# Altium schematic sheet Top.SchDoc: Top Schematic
size A4; Date: Not used; ApprovedBy: Not used; CheckedBy: Not used; Author: Not used; CompanyName: STMicroelectronics; DrawnBy: Not used; Engineer: Not used; Organization: Not used; Address1: Not used; Address2: Not used; Address3: Not used; Address4: Not used; DocumentNumber: Not used; Revision: Not used; SheetNumber: 2; SheetTotal: 6
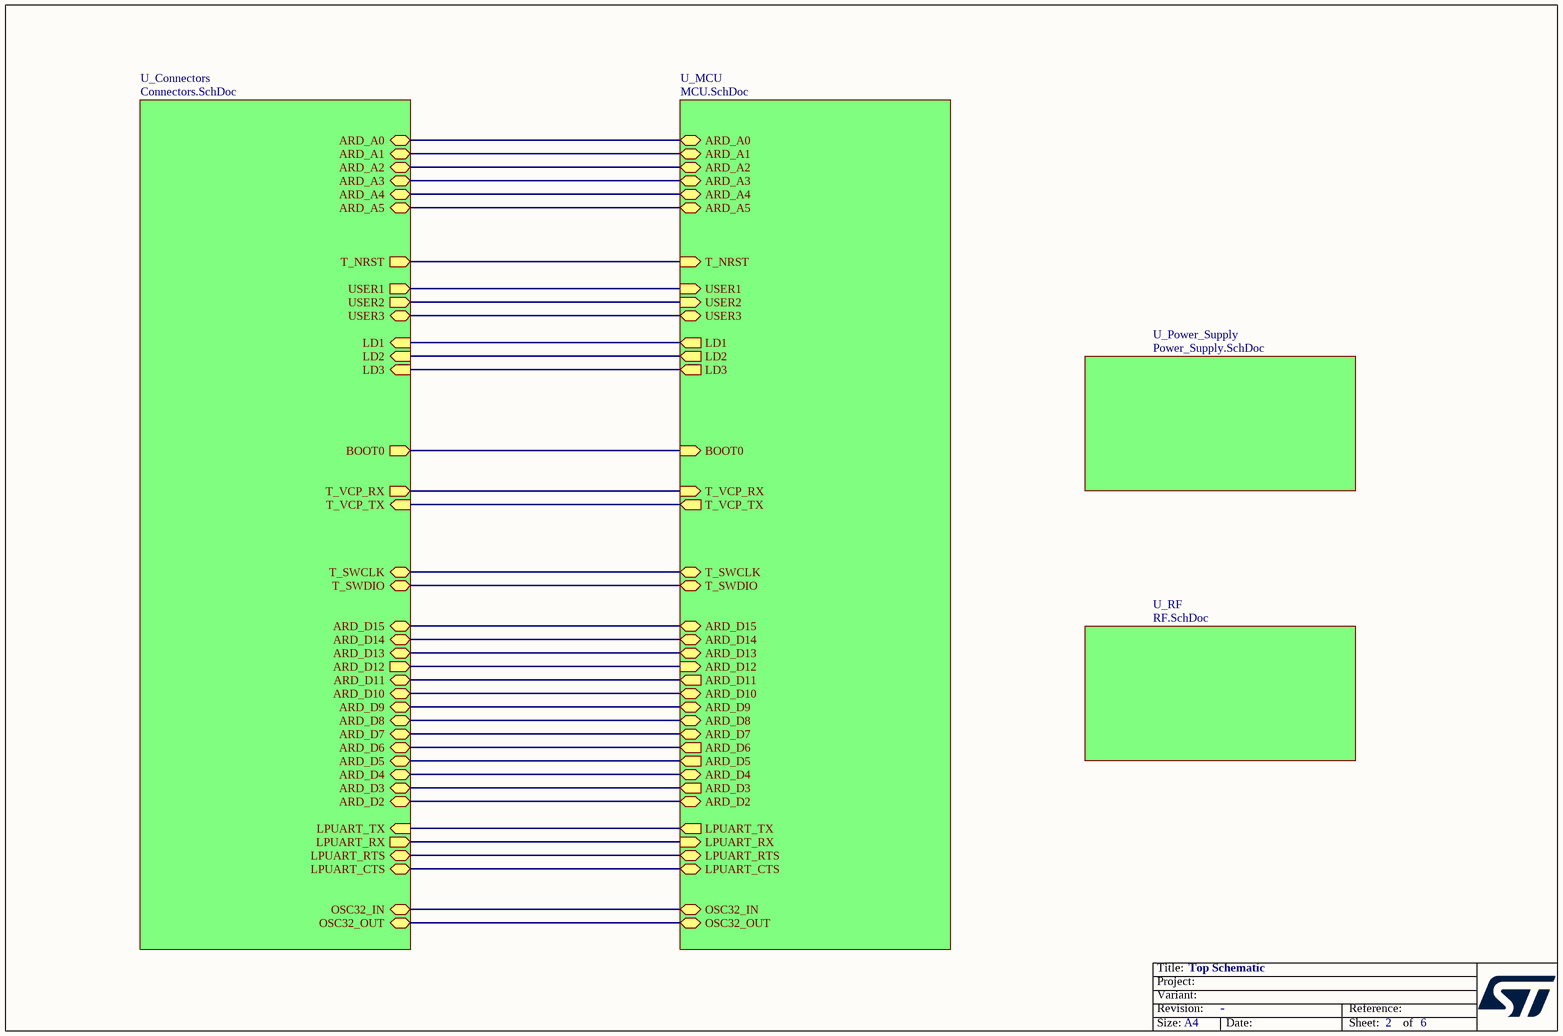
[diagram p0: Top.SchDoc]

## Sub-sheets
U_Connectors = Connectors.SchDoc: LD3 (in), LD1 (in), T_VCP_TX (in), T_SWCLK (bidir), T_SWDIO (bidir), T_VCP_RX (out), T_NRST (out), LD2 (in), OSC32_IN (bidir), OSC32_OUT (bidir), USER2 (out), USER1 (out), BOOT0 (out), ARD_D2 (bidir), USER3 (bidir), ARD_D9 (bidir), ARD_D13 (bidir), ARD_D10 (bidir), ARD_D12 (out), ARD_D14 (bidir), ARD_D15 (bidir), ARD_D11 (bidir), ARD_D8 (bidir), ARD_A1 (bidir), ARD_A0 (bidir), ARD_A2 (bidir), ARD_A3 (bidir), ARD_A4 (bidir), ARD_A5 (bidir), ARD_D7 (bidir), ARD_D6 (bidir), ARD_D3 (bidir), ARD_D4 (bidir), ARD_D5 (bidir), LPUART_TX (in), LPUART_RX (out), LPUART_RTS (bidir), LPUART_CTS (bidir)
U_MCU = MCU.SchDoc: T_NRST (in), LD2 (out), LD3 (out), LD1 (out), T_VCP_RX (in), T_SWCLK (bidir), T_SWDIO (bidir), T_VCP_TX (out), USER2 (in), USER1 (in), OSC32_OUT (bidir), OSC32_IN (bidir), BOOT0 (in), ARD_D2 (bidir), USER3 (bidir), ARD_D9 (bidir), ARD_D14 (bidir), ARD_D15 (bidir), ARD_D8 (bidir), ARD_D12 (in), ARD_D13 (bidir), ARD_A3 (bidir), ARD_A2 (bidir), ARD_A1 (bidir), ARD_A0 (bidir), ARD_A4 (bidir), ARD_A5 (bidir), ARD_D5 (out), ARD_D3 (out), ARD_D6 (out), ARD_D11 (out), ARD_D10 (bidir), ARD_D7 (bidir), ARD_D4 (bidir), LPUART_TX (out), LPUART_RX (in), LPUART_RTS (bidir), LPUART_CTS (bidir)
U_Power_Supply = Power_Supply.SchDoc: no entries
U_RF = RF.SchDoc: no entries

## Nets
(unnamed): sheet U_Connectors/LD3, sheet U_MCU/LD3
(unnamed): sheet U_Connectors/LD1, sheet U_MCU/LD1  [a separate net that carries the same name]
(unnamed): sheet U_Connectors/T_VCP_TX, sheet U_MCU/T_VCP_TX  [a separate net that carries the same name]
(unnamed): sheet U_Connectors/T_SWCLK, sheet U_MCU/T_SWCLK  [a separate net that carries the same name]
(unnamed): sheet U_Connectors/T_SWDIO, sheet U_MCU/T_SWDIO  [a separate net that carries the same name]
(unnamed): sheet U_Connectors/T_VCP_RX, sheet U_MCU/T_VCP_RX  [a separate net that carries the same name]
(unnamed): sheet U_Connectors/T_NRST, sheet U_MCU/T_NRST  [a separate net that carries the same name]
(unnamed): sheet U_Connectors/LD2, sheet U_MCU/LD2  [a separate net that carries the same name]
(unnamed): sheet U_Connectors/OSC32_IN, sheet U_MCU/OSC32_IN  [a separate net that carries the same name]
(unnamed): sheet U_Connectors/OSC32_OUT, sheet U_MCU/OSC32_OUT  [a separate net that carries the same name]
(unnamed): sheet U_Connectors/USER2, sheet U_MCU/USER2  [a separate net that carries the same name]
(unnamed): sheet U_Connectors/USER1, sheet U_MCU/USER1  [a separate net that carries the same name]
(unnamed): sheet U_Connectors/BOOT0, sheet U_MCU/BOOT0  [a separate net that carries the same name]
(unnamed): sheet U_Connectors/ARD_D2, sheet U_MCU/ARD_D2  [a separate net that carries the same name]
(unnamed): sheet U_Connectors/USER3, sheet U_MCU/USER3  [a separate net that carries the same name]
(unnamed): sheet U_Connectors/ARD_D9, sheet U_MCU/ARD_D9  [a separate net that carries the same name]
(unnamed): sheet U_Connectors/ARD_D13, sheet U_MCU/ARD_D13  [a separate net that carries the same name]
(unnamed): sheet U_Connectors/ARD_D10, sheet U_MCU/ARD_D10  [a separate net that carries the same name]
(unnamed): sheet U_Connectors/ARD_D12, sheet U_MCU/ARD_D12  [a separate net that carries the same name]
(unnamed): sheet U_Connectors/ARD_D14, sheet U_MCU/ARD_D14  [a separate net that carries the same name]
(unnamed): sheet U_Connectors/ARD_D15, sheet U_MCU/ARD_D15  [a separate net that carries the same name]
(unnamed): sheet U_Connectors/ARD_D11, sheet U_MCU/ARD_D11  [a separate net that carries the same name]
(unnamed): sheet U_Connectors/ARD_D8, sheet U_MCU/ARD_D8  [a separate net that carries the same name]
(unnamed): sheet U_Connectors/ARD_A1, sheet U_MCU/ARD_A1  [a separate net that carries the same name]
(unnamed): sheet U_Connectors/ARD_A0, sheet U_MCU/ARD_A0  [a separate net that carries the same name]
(unnamed): sheet U_Connectors/ARD_A2, sheet U_MCU/ARD_A2  [a separate net that carries the same name]
(unnamed): sheet U_Connectors/ARD_A3, sheet U_MCU/ARD_A3  [a separate net that carries the same name]
(unnamed): sheet U_Connectors/ARD_A4, sheet U_MCU/ARD_A4  [a separate net that carries the same name]
(unnamed): sheet U_Connectors/ARD_A5, sheet U_MCU/ARD_A5  [a separate net that carries the same name]
(unnamed): sheet U_Connectors/ARD_D7, sheet U_MCU/ARD_D7  [a separate net that carries the same name]
(unnamed): sheet U_Connectors/ARD_D6, sheet U_MCU/ARD_D6  [a separate net that carries the same name]
(unnamed): sheet U_Connectors/ARD_D3, sheet U_MCU/ARD_D3  [a separate net that carries the same name]
(unnamed): sheet U_Connectors/ARD_D4, sheet U_MCU/ARD_D4  [a separate net that carries the same name]
(unnamed): sheet U_Connectors/ARD_D5, sheet U_MCU/ARD_D5  [a separate net that carries the same name]
(unnamed): sheet U_Connectors/LPUART_TX, sheet U_MCU/LPUART_TX  [a separate net that carries the same name]
(unnamed): sheet U_Connectors/LPUART_RX, sheet U_MCU/LPUART_RX  [a separate net that carries the same name]
(unnamed): sheet U_Connectors/LPUART_RTS, sheet U_MCU/LPUART_RTS  [a separate net that carries the same name]
(unnamed): sheet U_Connectors/LPUART_CTS, sheet U_MCU/LPUART_CTS  [a separate net that carries the same name]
